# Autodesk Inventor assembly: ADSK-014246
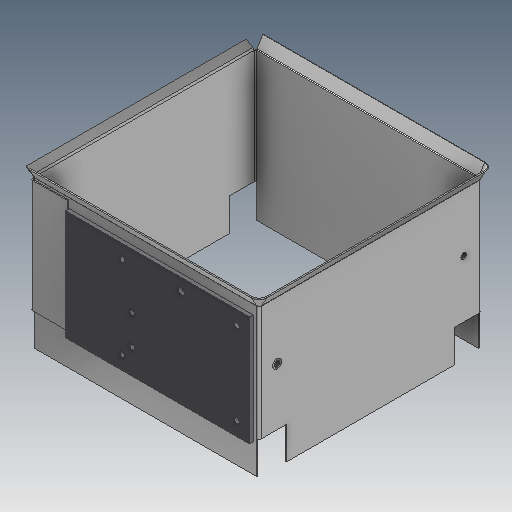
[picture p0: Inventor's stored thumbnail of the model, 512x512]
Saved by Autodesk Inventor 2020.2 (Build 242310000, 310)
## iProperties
Created: 1999-12
Part Number: ADSK-014246
Document SubType Name: Assembly
Designer: glanglot
Mass: 4038.98 g
Surface Area: 6461.55 cm^2
Volume: 611.024 cm^3
Density: 6.61019 g/cm^3
Control State: 0
Checked Out: False
Master: False
Shininess: 0.0
Length Units: 11269
Angle Units: 11279
Time Units: 11290
Mass Units: 11283
Length Display Precision: 3
Angle Display Precision: 2
Compacted: True
Dimensions: 332,2x218,6x323,8 mm
Mass: 4,039 kg
DocNumber: ADSK-014246
Folder: 01 - Themengebiete\Simplification\01 - Packaging machine\
Original: C:\AB_Vault\CAD\01 - Themengebiete\Simplification\01 - Packaging machine\500383.iam
VDS_Category: 3D Komponenten
VDS_NumSchm: Autodesk
Density: 0.0
Volumn: 0.0
Area: 0.0
PropertySet Name: Model Information
Author: glanglot
Revision Number: -
Title: box
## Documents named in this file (5)
- D:\07 - DEMODATEN\OTX 2019 - Dataset - UPDATE - Dez2019\Designs\07-Packing machine\ADSK-014246.iam
- D:\07 - DEMODATEN\OTX 2019 - Dataset - UPDATE - Dez2019\Designs\07-Packing machine\Parts\ADSK-011372.ipt
- D:\07 - DEMODATEN\OTX 2019 - Dataset - UPDATE - Dez2019\Designs\07-Packing machine\Parts\ADSK-011370.ipt
- D:\07 - DEMODATEN\OTX 2019 - Dataset - UPDATE - Dez2019\Designs\07-Packing machine\Parts\ADSK-011371.ipt
- D:\07 - DEMODATEN\OTX 2019 - Dataset - UPDATE - Dez2019\Designs\07-Packing machine\Parts\ADSK-011373.ipt
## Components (5 placed, 4 different names)
1. ADSK-011370:1 — Passend:1, Fluchtend:1, Passend:2, Flush:2, Flush:3, Mate:3, Einfügen:1, Insert:2, Fluchtend:4, Fluchtend:5, Passend:5
2. ADSK-011371:1 — Passend:1, Fluchtend:1, Passend:2
3. ADSK-011372:1 — Einfügen:1
4. ADSK-011372:2 — Insert:2
5. ADSK-011373:1 — Fluchtend:4, Fluchtend:5, Passend:5
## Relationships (11: Flush 5, Mate 4, Insert 2)
- Passend:1 [Mate]: ADSK-011370:1 ↔ ADSK-011371:1
- Fluchtend:1 [Flush]: ADSK-011370:1 ↔ ADSK-011371:1
- Passend:2 [Mate]: ADSK-011370:1 ↔ ADSK-011371:1
- Flush:2: ADSK-011370:1
- Flush:3: ADSK-011370:1
- Mate:3: ADSK-011370:1
- Einfügen:1 [Insert]: ADSK-011370:1 ↔ ADSK-011372:1
- Insert:2: ADSK-011370:1 ↔ ADSK-011372:2
- Fluchtend:4 [Flush]: ADSK-011370:1 ↔ ADSK-011373:1
- Fluchtend:5 [Flush]: ADSK-011370:1 ↔ ADSK-011373:1
- Passend:5 [Mate]: ADSK-011370:1 ↔ ADSK-011373:1
